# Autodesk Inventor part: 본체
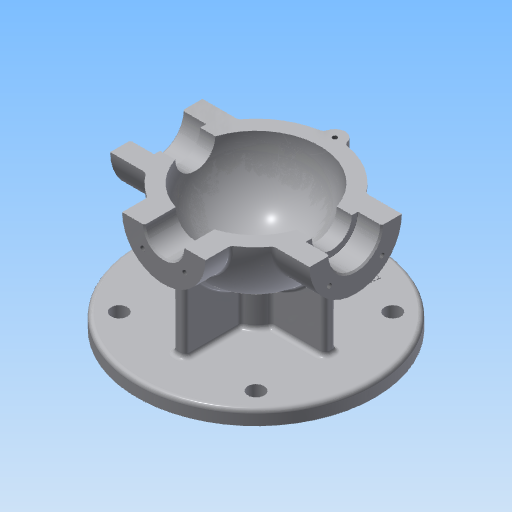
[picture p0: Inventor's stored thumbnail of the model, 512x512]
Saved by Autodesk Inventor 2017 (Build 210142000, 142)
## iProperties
Created: 2015-12
Part Number: 본체
Material: 알루미늄 6061
Document SubType Name: Modeling
Designer: mduedu
Density: 2.71 g/cm^3
Appearance: 알루미늄 - 평지
Mass: 1042.75 g
Surface Area: 959.747 cm^2
Volume: 384.78 cm^3
Author: mduedu
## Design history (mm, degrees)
sketch "스케치1"
  geometry: L1 (-53, 0)-(53, 0); A1 r 53 centre (0, 0) between (53, 0) and (-53, 0); 2 further points
  constraints: 2 coincident, 2 end point, 2 point on circle, 1 centre point, 1 horizontal, 1 midpoint
  dimensions: "d0" = 53 radius of A1
revolve "회전1" sketch "스케치1" stored, may be unused: angle "d2" = 90 deg
feature "쉘1" dims "d11" = 10
node "작업 평면1"
sketch "스케치2"
  geometry: C1 r 31 at (0, 0); 1 further point
  constraints: 1 centre point, 1 coincident
  dimensions: "d4" = 62 diameter of C1
extrude "돌출1" join sketch "스케치2" stored distance "d5" = 10; taper "d6" = 0 deg
node "작업 평면2"
sketch "스케치3"
  geometry: C1 r 28 at (0, 0); 1 further point
  constraints: 1 centre point, 1 coincident
  dimensions: "d8" = 56 diameter of C1
extrude "돌출2" join sketch "스케치3" stored distance "d9" = 10; taper "d10" = 0 deg
hole "구멍1" diameter "d14" = 35; stored, may be unused: countersink angle "d18" = 90 deg, drill point angle "d20" = 0 deg; dims "d12" = 10, "d13" = 10, "d15" = 6, "d16" = 4, "d17" = 2, "d19" = 16
hole "구멍2" diameter "d23" = 27; stored, may be unused: countersink angle "d27" = 90 deg, drill point angle "d29" = 0 deg; dims "d21" = 10, "d22" = 10, "d24" = 6, "d25" = 4, "d26" = 2, "d28" = 16
fillet "모깎기1" dims "d30" = 0.3
hole "구멍3" diameter "d33" = 26; stored, may be unused: countersink angle "d37" = 90 deg, drill point angle "d39" = 0 deg; dims "d31" = 10, "d32" = 10, "d34" = 6, "d35" = 4, "d36" = 2, "d38" = 16
chamfer "모따기1" distance "d40" = 1; stored, may be unused: second distance "d41" = 2, angle "d42" = 45 deg
sketch "스케치4"
  geometry: L1 (0, 0)-(0, -25); L2 (0, 0)-(-17.678, -17.678); A1 r 25 centre (0, 0) between (-17.678, -17.678) and (0, -25); 1 further point
  constraints: 4 end point, 2 point on circle, 1 centre point, 1 coincident, 1 vertical
  dimensions: "d43" = 50 diameter of A1; "d47" = 45 deg angle of L1 L2
hole "구멍4" sketch "스케치4" at (-17.678, -17.678) diameter "d49" = 3.242; stored, may be unused: countersink angle "d53" = 90 deg, drill point angle "d55" = 118 deg; dims "d50" = 11, "d51" = 4, "d52" = 2, "d54" = 13
sketch "스케치5"
  geometry: L1 (0, 0)-(0, -20); L2 (0, 0)-(-14.142, -14.142); A1 r 20 centre (0, 0) between (0, -20) and (-14.142, -14.142); 2 further points
  constraints: 4 end point, 2 coincident, 2 point on circle, 1 centre point, 1 vertical
  dimensions: "d59" = 40 diameter of A1; "d65" = 45 deg angle of L1 L2
hole "구멍5" sketch "스케치5" at (-14.142, -14.142) diameter "d67" = 3.242; stored, may be unused: countersink angle "d71" = 90 deg, drill point angle "d73" = 118 deg; dims "d68" = 8, "d69" = 4, "d70" = 2, "d72" = 10
node "작업 평면3"
sketch "스케치6"
  geometry: C1 r 80 at (0, 0); 1 further point
  constraints: 1 centre point, 1 coincident
  dimensions: "d78" = 160 diameter of C1
extrude "돌출3" join sketch "스케치6" distance "d80" = 10; taper "d81" = 0 deg
sketch "스케치7"
  geometry: C1 r 15 at (0, 0); 1 further point
  constraints: 1 centre point, 1 coincident
  dimensions: "d82" = 30 diameter of C1
extrude "돌출4" join sketch "스케치7" stored distance "d84" = 10; taper "d85" = 0 deg
sketch "스케치8"
  geometry: 2 further points
  constraints: 1 coincident
hole "구멍6" sketch "스케치8" at (0, 0) diameter "d86" = 20; stored, may be unused: countersink angle "d90" = 90 deg, drill point angle "d92" = 118 deg; dims "d87" = 7, "d88" = 100, "d89" = 5, "d91" = 10
fillet "모깎기2" dims "d93" = 0.3
sketch "스케치9"
  geometry: L1 (-67, -18.5)-(-66, -17.5) reference; L2 (-66, -17.5)-(-51.3, -17.5) reference; L3 (-51, -17.2)-(-51, -13.5) reference; L4 (-51, -13.5)-(-40.826, -13.5) reference; L5 (-10, -41.821)-(-10, -80) reference; L6 (-10, -80)-(-49.7, -80) reference; L7 (-50, -80.3)-(-50, -85) reference; L8 (-50, -85)-(-80, -85) reference; L9 (-80, -85)-(-80, -75) reference; L10 (-80, -75)-(-15, -75) reference; L11 (-15, -75)-(-15, -50.833) reference; L12 (-42.988, -31)-(-67, -31) reference; L13 (-67, -31)-(-67, -18.5) reference; L14 (66, -17.5)-(67, -18.5) reference; L15 (67, -18.5)-(67, -31) reference; L16 (67, -31)-(42.988, -31) reference; L17 (15, -50.833)-(15, -75) reference; L18 (15, -75)-(80, -75) reference; L19 (80, -75)-(80, -85) reference; L20 (80, -85)-(50, -85) reference; L21 (50, -85)-(50, -80.3) reference; L22 (49.7, -80)-(10, -80) reference; L23 (10, -80)-(10, -41.821) reference; L24 (40.826, -13.5)-(51, -13.5) reference; L25 (51, -13.5)-(51, -17.2) reference; L26 (51.3, -17.5)-(66, -17.5) reference; L27 (67, 18.5)-(66, 17.5) reference; L28 (66, 17.5)-(51.3, 17.5) reference; L29 (51, 17.2)-(51, 13.5) reference; L30 (51, 13.5)-(40.826, 13.5) reference; L31 (-40.826, 13.5)-(-51, 13.5) reference; L32 (-51, 13.5)-(-51, 17.2) reference; L33 (-51.3, 17.5)-(-66, 17.5) reference; L34 (-66, 17.5)-(-67, 18.5) reference; L35 (-67, 18.5)-(-67, 31) reference; L36 (-67, 31)-(-42.988, 31) reference; L37 (42.988, 31)-(67, 31) reference; L38 (67, 31)-(67, 18.5) reference; L39 (-50, -31)-(-50, -75); A1 r 0.3 centre (-51.3, -17.2) between (-51.3, -17.5) and (-51, -17.2) reference; A2 r 43 centre (0, 0) between (-40.826, -13.5) and (-10, -41.821) reference; A3 r 0.3 centre (-49.7, -80.3) between (-49.7, -80) and (-50, -80.3) reference; A4 r 53 centre (0, 0) between (-42.988, -31) and (-15, -50.833) reference; A5 r 53 centre (0, 0) between (15, -50.833) and (42.988, -31) reference; A6 r 0.3 centre (49.7, -80.3) between (50, -80.3) and (49.7, -80) reference; A7 r 43 centre (0, 0) between (10, -41.821) and (40.826, -13.5) reference; A8 r 0.3 centre (51.3, -17.2) between (51, -17.2) and (51.3, -17.5) reference; A9 r 0.3 centre (51.3, 17.2) between (51.3, 17.5) and (51, 17.2) reference; A10 r 43 centre (0, 0) between (40.826, 13.5) and (-40.826, 13.5) reference; A11 r 0.3 centre (-51.3, 17.2) between (-51, 17.2) and (-51.3, 17.5) reference; A12 r 53 centre (0, 0) between (42.988, 31) and (-42.988, 31) reference; 1 further point
  constraints: 2 end point, 2 point on line
  dimensions: "d173" = 30 distance from line of L39.end L9; "d174" = 90 deg angle of L10 L39
feature "리브1" sketch "스케치9" dims "d96" = 1, "d97" = 8, "d98" = 0, "d99" = 0, "d100" = 1, "d101" = 1
sketch "스케치14"
  geometry: L1 (-14, 62)-(-13, 61) reference; L2 (-13, 61)-(-13, 40.988) reference; L3 (-41.821, 10)-(-80, 10) reference; L4 (-80, 10)-(-80, 49.7) reference; L5 (-80.3, 50)-(-85, 50) reference; L6 (-85, 50)-(-85, 80) reference; L7 (-85, 80)-(-75, 80) reference; L8 (-75, 80)-(-75, 15) reference; L9 (-75, 15)-(-50.833, 15) reference; L10 (-28, 45)-(-28, 62) reference; L11 (-28, 62)-(-14, 62) reference; L12 (13, 61)-(14, 62) reference; L13 (14, 62)-(28, 62) reference; L14 (28, 62)-(28, 45) reference; L15 (-50.833, -15)-(-75, -15) reference; L16 (-75, -15)-(-75, -80) reference; L17 (-75, -80)-(-85, -80) reference; L18 (-85, -80)-(-85, -50) reference; L19 (-85, -50)-(-80.3, -50) reference; L20 (-80, -49.7)-(-80, -10) reference; L21 (-80, -10)-(-41.821, -10) reference; L22 (13, 40.988)-(13, 61) reference; L23 (-28, 52)-(-75, 52); A1 r 43 centre (0, 0) between (-13, 40.988) and (-41.821, 10) reference; A2 r 0.3 centre (-80.3, 49.7) between (-80, 49.7) and (-80.3, 50) reference; A3 r 53 centre (0, 0) between (-28, 45) and (-50.833, 15) reference; A4 r 53 centre (0, 0) between (0, -53) and (28, 45) reference; A5 r 53 centre (0, 0) between (-50.833, -15) and (0, -53) reference; A6 r 0.3 centre (-80.3, -49.7) between (-80.3, -50) and (-80, -49.7) reference; A7 r 43 centre (0, 0) between (-41.821, -10) and (0, -43) reference; A8 r 43 centre (0, 0) between (0, -43) and (13, 40.988) reference; 1 further point
  constraints: 2 end point, 2 point on line
  dimensions: "d175" = 28 distance of L7.end L23.end; "d176" = 90 deg angle of L8 L23
feature "리브2" sketch "스케치14" dims "d153" = 1, "d154" = 8, "d155" = 0, "d156" = 0, "d157" = 1, "d158" = 1
sketch "스케치10"
  geometry: L1 (0, 0)-(0, -65); L2 (0, 0)-(-45.962, -45.962); A1 r 65 centre (0, 0) between (0, -65) and (-45.962, -45.962); 2 further points
  constraints: 4 end point, 2 coincident, 2 point on circle, 1 centre point, 1 vertical
  dimensions: "d105" = 130 diameter of A1; "d107" = 45 deg angle of L1 L2
hole "구멍7" sketch "스케치10" at (-45.962, -45.962) diameter "d109" = 11; stored, may be unused: countersink angle "d113" = 90 deg, drill point angle "d115" = 118 deg; dims "d110" = 7, "d111" = 18, "d112" = 4, "d114" = 10
fillet "모깎기3" dims "d120" = 3
fillet "모깎기4" dims "d121" = 3, "d122" = 3
fillet "모깎기5" dims "d123" = 3
fillet "모깎기6" dims "d124" = 3
sketch "스케치11"
  geometry: C1 r 80 at (0, 0) reference; C2 r 65 at (0, 0)
  constraints: 1 centre point, 1 coincident, 1 other
  dimensions: "d161" = 130 diameter of C2
feature "엠보싱1" sketch "스케치11" dims "d11" = 10, "d125" = 0.5, "d126" = 0
sketch "스케치12"
  geometry: L1 (0, 100)-(0, -100); L2 (0, 100)-(100, 100); L3 (100, 100)-(100, -100); L4 (100, -100)-(0, -100); 2 further points
  constraints: 8 end point, 3 perpendicular, 1 coincident, 1 midpoint, 1 vertical
  dimensions: "d127" = 200 distance of L2.end L3.end; "d129" = 100 distance between parallel lines of L1 L3
extrude "돌출5" cut sketch "스케치12" stored distance "d130" = 10; taper "d131" = 0 deg
sketch "스케치13"
  geometry: C1 r 7 at (0, 53); A1 r 53 centre (0, 0) between (42.113, 32.179) and (-42.113, 32.179) reference; 1 further point
  constraints: 1 centre point, 1 point on circle
  dimensions: "d132" = 14 diameter of C1
extrude "돌출6" join sketch "스케치13" distance "d134" = 15; taper "d135" = 0 deg
hole "구멍8" diameter "d139" = 3.242; stored, may be unused: countersink angle "d143" = 90 deg, drill point angle "d145" = 118 deg; dims "d140" = 8, "d141" = 4, "d142" = 2, "d144" = 10, "d148" = 10, "d149" = 10
fillet "모깎기7" dims "d146" = 3
fillet "모깎기8" dims "d147" = 3
node "솔리드1"
mirror "대칭1"
mirror "대칭2"
pattern_circular "원형 패턴1" dims angle "d57" = 360 deg
mirror "대칭3"
pattern_circular "원형 패턴2" dims angle "d75" = 360 deg
mirror "대칭4"
pattern_circular "원형 패턴4" dims angle "d118" = 360 deg
node "절단 모서리 투영1"
node "절단 모서리 투영2"
other parameters: "d3" = 67, "d7" = 62, "d77" = -85
